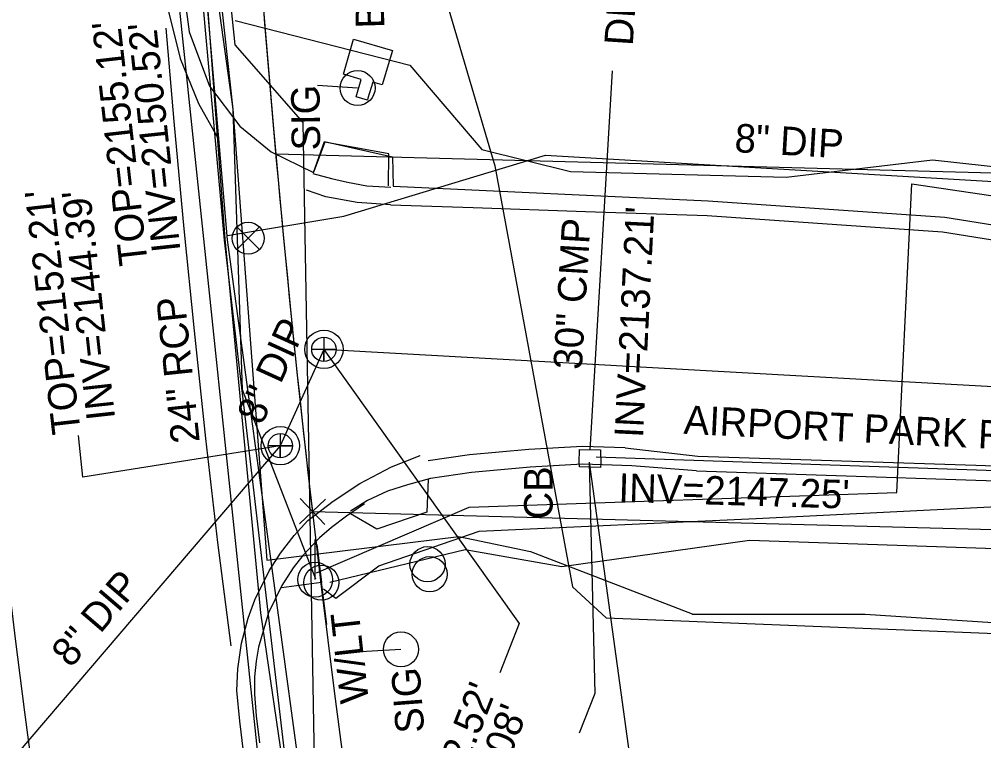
# Model space of a CAD drawing. Extents: x 945964 to 948456, y 631061 to 636061.
# Drawn here: x 946824.1 to 946959.3, y 632629.6 to 632730.8 of the extents above; entities that cross this region are included whole.
import ezdxf

# ---------------------------------------------------------------- set-up
doc = ezdxf.new("R2010")
doc.units = 0
for name, color, linetype in [('Exist Boundary County Line', 7, 'Continuous'), ('Exist Horizontal Alignment', 7, 'Continuous'), ('Exist Other Culture Area Outline', 7, 'Continuous'), ('Exist Other Culture Area Outline Text', 7, 'Continuous'), ('Exist Property Corner CELL', 7, 'Continuous'), ('Exist Property Line', 7, 'Continuous'), ('Exist Right of Way Line', 7, 'Continuous'), ('Exist Roads Curbs', 7, 'Continuous'), ('Exist Roads EOP', 7, 'Continuous'), ('Exist Roads EOP Other', 7, 'Continuous'), ('Exist Roads EOP Text', 7, 'Continuous'), ('Exist Roads EOT', 7, 'Continuous'), ('Exist Structure Minor Catch Basin', 7, 'Continuous'), ('Exist Structure Minor Catch Basin Text', 7, 'Continuous'), ('Exist Structure Minor Catch Basin Top Elevation', 7, 'Continuous'), ('Exist Structure Minor Pipes CMP 24 Inch', 7, 'Continuous'), ('Exist Structure Minor Pipes CMP 24 Inch Invert', 7, 'Continuous'), ('Exist Structure Minor Pipes CMP 30 Inch', 7, 'Continuous'), ('Exist Structure Minor Pipes CMP 30 Inch Invert', 7, 'Continuous'), ('Exist Structure Minor Pipes CMP 30 Inch Text', 7, 'Continuous'), ('Exist Structure Minor Pipes RCP 24 Inch', 7, 'Continuous'), ('Exist Structure Minor Pipes RCP 24 Inch Invert', 7, 'Continuous'), ('Exist Structure Minor Pipes RCP 24 Inch Text', 7, 'Continuous'), ('Exist Utilities Gas UG Line SUE', 7, 'Continuous'), ('Exist Utilities Other Pole CELL', 7, 'Continuous'), ('Exist Utilities Other Pole Text', 7, 'Continuous'), ('Exist Utilities Power Joint Use Telephone CELL', 7, 'Continuous'), ('Exist Utilities Power Joint Use Telephone Text', 7, 'Continuous'), ('Exist Utilities Power Pole CELL', 7, 'Continuous'), ('Exist Utilities Power UG Cable SUE', 7, 'Continuous'), ('Exist Utilities Sanitary Sewer Manhole CELL', 7, 'Continuous'), ('Exist Utilities Sanitary Sewer Manhole Leader', 7, 'Continuous'), ('Exist Utilities Sanitary Sewer Manhole Text', 7, 'Continuous'), ('Exist Utilities Sanitary Sewer UG Line', 7, 'Continuous'), ('Exist Utilities Sanitary Sewer UG Line Invert Elevation', 7, 'Continuous'), ('Exist Utilities Sanitary Sewer UG Line Text', 7, 'Continuous'), ('Exist Utilities Telephone UG Cable SUE', 7, 'Continuous'), ('Exist Utilities Telephone UG FO SUE', 7, 'Continuous'), ('Exist Utilities TV UG Cable SUE', 7, 'Continuous'), ('Exist Utilities Water UG Line SUE', 7, 'Continuous'), ('Exist Utilities Water UG Line SUE Text', 7, 'Continuous'), ('Exist Utilities Water Valve CELL', 7, 'Continuous')]:
    doc.layers.add(name, color=color, linetype=linetype)

# ---------------------------------------------------------------- blocks, each defined once
blk = doc.blocks.new('EXIST UTILITIES POWER POLE')
at = {"layer": 'Exist Utilities Power Pole CELL'}
for q in [(0, 0.1125), (0, 0)]:
    blk.add_line((0, 0), q, dxfattribs=at)
blk.add_circle((0, 0), 0.049, dxfattribs=at)
blk = doc.blocks.new('EXIST UTILITIES POWER JOINT USE TELEPHONE')
at = {"layer": 'Exist Utilities Power Joint Use Telephone CELL'}
blk.add_line((0, 0), (0, 0), dxfattribs=at)
blk.add_lwpolyline([(-0.1188, 0), (0.108, -0.0008), (0, -0.0004), (0, 0.1125)], dxfattribs=at)
blk.add_circle((0, 0.0001), 0.049, dxfattribs=at)

msp = doc.modelspace()

# ---------------------------------------------------------------- linework, layer by layer
at = {"layer": 'Exist Boundary County Line'}
msp.add_line((946865.22, 632661.77), (947116.03, 632655.16), dxfattribs=at)
msp.add_arc((948848.33, 632890.69), 1996.28, 184.06017, 186.58486, dxfattribs=at)
at = {"layer": 'Exist Horizontal Alignment'}
msp.add_arc((948718.82, 632879.65), 1909.86, 158.53343, 198.31343, dxfattribs=at)
at = {"layer": 'Exist Other Culture Area Outline'}
msp.add_lwpolyline([(946876.44, 632726.41), (946875, 632721.59), (946873.67, 632721.98), (946873.01, 632719.73), (946872.93, 632719.46), (946871.36, 632719.91), (946872.07, 632722.35), (946869.57, 632723.08), (946870.99, 632728)], close=True, dxfattribs=at)
at = {"layer": 'Exist Property Corner CELL'}
msp.add_line((946865.22, 632661.77), (946865.22, 632661.77), dxfattribs=at)
msp.add_lwpolyline([(946867.04, 632663.49), (946863.41, 632660.05), (946865.22, 632661.77), (946866.94, 632659.96), (946863.5, 632663.58)], dxfattribs=at)
at = {"layer": 'Exist Property Line'}
msp.add_line((946865.22, 632661.77), (947116.03, 632655.16), dxfattribs=at)
at = {"layer": 'Exist Right of Way Line'}
msp.add_line((946860.08, 632711.92), (947121.14, 632705.04), dxfattribs=at)
for radius, start in [(2096.28, 158.90258), (1996.28, 171.75828)]:
    msp.add_arc((948848.33, 632890.69), radius, start, 198.31343, dxfattribs=at)
at = {"layer": 'Exist Roads Curbs'}
for points in [[(946846.62, 632738.85), (946847.93, 632729), (946850.81, 632721.41), (946850.81, 632721.41), (946855.05, 632715.78), (946855.05, 632715.78), (946859.42, 632712.2), (946859.42, 632712.2), (946865.36, 632709.28), (946865.36, 632709.28), (946866.9, 632713.62), (946876.43, 632711.51), (946876.56, 632707.39), (946920.69, 632705.34)], [(946865.29, 632709.15), (946867.89, 632708.44), (946870.16, 632707.94), (946872.87, 632707.41), (946876.24, 632707.26)], [(946920.69, 632705.34), (946953.92, 632703.03), (946991.05, 632697.11), (947030.54, 632691.4), (947077.23, 632689.71), (947108.79, 632688.67), (947121.81, 632688.32)], [(946919.09, 632667.47), (946910.02, 632668.15), (946903.11, 632668.39), (946895.77, 632667.98), (946887.55, 632667.22), (946881.8, 632666.39)], [(946919.09, 632667.47), (946958.23, 632666.16), (946999.64, 632664.8), (947044.7, 632663.37), (947090.93, 632661.91), (947118.18, 632660.82)], [(946881.8, 632666.39), (946878.57, 632665.49), (946875.76, 632664.6), (946872.94, 632663.29), (946870.57, 632661.79)], [(946872.52, 632662.84), (946869.98, 632661.09), (946867.88, 632659.53), (946866.21, 632658.08), (946866.21, 632658.08), (946863.86, 632655.59), (946863.86, 632655.59), (946862.54, 632653.88), (946862.54, 632653.88), (946860.93, 632651.38), (946860.93, 632651.38), (946859.08, 632647.54), (946859.08, 632647.54), (946857.66, 632642.73), (946857.66, 632642.73), (946857.33, 632640.77), (946857.33, 632640.77), (946857.12, 632638.57), (946857.12, 632638.57), (946857.08, 632636.17), (946857.08, 632636.17), (946857.33, 632633.12), (946857.33, 632633.12), (946857.79, 632629.35)]]:
    msp.add_lwpolyline(points, dxfattribs=at)
at = {"layer": 'Exist Roads EOP'}
for points in [[(946838.69, 632880.41), (946838.99, 632838.5), (946840.08, 632810.26), (946840.15, 632806.84), (946841.49, 632776.12), (946844.15, 632739.37), (946844.51, 632735.59), (946844.98, 632732.05), (946844.98, 632732.05), (946846.66, 632725.29), (946846.66, 632725.29), (946849.24, 632718.98), (946849.24, 632718.98), (946851.83, 632714.41), (946851.83, 632714.41)], [(946876.16, 632704.76), (946871.48, 632705.09), (946867.08, 632705.87), (946864.37, 632706.82)], [(946876.16, 632704.76), (946887.77, 632704.41), (946903.52, 632703.82), (946920.55, 632703.29)], [(946920.55, 632703.29), (946953.58, 632701), (946990.71, 632695.02), (947030.31, 632689.26), (947077.14, 632687.69), (947098.06, 632686.95), (947118.43, 632686.6), (947118.43, 632686.16), (947121.73, 632685.88), (947121.74, 632686.3), (947123.84, 632686.1)], [(946909.07, 632670.69), (946903.08, 632670.89), (946895.59, 632670.47), (946887.25, 632669.71), (946881.44, 632668.87)], [(946909.07, 632670.69), (946919.28, 632669.53)], [(946855.54, 632628.11), (946855.05, 632632.37), (946854.61, 632636.67), (946854.76, 632639.69), (946854.76, 632639.69), (946855.3, 632643.3), (946855.3, 632643.3), (946856.22, 632646.8), (946856.22, 632646.8), (946857.17, 632649.4), (946857.17, 632649.4), (946859.17, 632653.46), (946859.17, 632653.46), (946860.74, 632655.93), (946860.74, 632655.93), (946862.65, 632658.41), (946862.65, 632658.41), (946864.58, 632660.49), (946864.58, 632660.49), (946866.36, 632661.87), (946868.11, 632663.22), (946868.11, 632663.22), (946871.87, 632665.71), (946871.87, 632665.71), (946876.3, 632668.01), (946876.3, 632668.01), (946880.35, 632669.62), (946880.35, 632669.62)], [(946919.28, 632669.53), (946958.23, 632668.27), (946999.9, 632666.82), (947044.72, 632665.42), (947090.96, 632663.98), (947118.77, 632662.77)]]:
    msp.add_lwpolyline(points, dxfattribs=at)
at = {"layer": 'Exist Roads EOP Other'}
for points in [[(946875.9, 632707.41), (946875.92, 632711.91), (946866.97, 632713.53), (946865.43, 632709.42)], [(946881.47, 632666.28), (946881.26, 632661.66), (946874.26, 632659.28), (946870.55, 632661.45)]]:
    msp.add_lwpolyline(points, dxfattribs=at)
at = {"layer": 'Exist Roads EOT'}
msp.add_lwpolyline([(946853.83, 632642.93), (946851.94, 632657.4), (946850.26, 632672.01), (946848.67, 632687.12), (946847.26, 632701.39), (946845.82, 632716.44), (946844.73, 632729.51)], dxfattribs=at)
at = {"layer": 'Exist Structure Minor Catch Basin'}
msp.add_line((946902.65, 632670.47), (946905.61, 632670.39), dxfattribs=at)
msp.add_lwpolyline([(946905.61, 632670.39), (946905.67, 632668.51), (946905.61, 632667.92), (946902.65, 632668.01), (946902.64, 632668.57), (946902.65, 632670.47)], dxfattribs=at)
at = {"layer": 'Exist Structure Minor Pipes CMP 24 Inch'}
msp.add_line((947119.08, 632662.1), (946905, 632669.37), dxfattribs=at)
at = {"layer": 'Exist Structure Minor Pipes CMP 30 Inch'}
for p, q in [((946904.18, 632670.38), (946907.31, 632723.54)), ((946904.02, 632668.67), (946928.64, 632489.27))]:
    msp.add_line(p, q, dxfattribs=at)
at = {"layer": 'Exist Structure Minor Pipes CMP 30 Inch Invert'}
msp.add_lwpolyline([(946904.02, 632668.67), (946904.8, 632636.27), (946902.61, 632630.68)], dxfattribs=at)
at = {"layer": 'Exist Structure Minor Pipes RCP 24 Inch'}
msp.add_line((946859.33, 632610.91), (946846.2, 632736.06), dxfattribs=at)
at = {"layer": 'Exist Utilities Gas UG Line SUE'}
for points in [[(946946.02, 632290.11), (946927.48, 632348.33), (946918.8, 632381.36), (946891.12, 632487.29), (946880.5, 632542.4), (946865.51, 632626.8), (946863.92, 632716.3), (946854.37, 632727.21), (946849.91, 632770.49), (946845.5, 632898.11)], [(946854.38, 632730.61), (946878.9, 632724.35), (946888.96, 632712.5), (946901.39, 632709.45), (946931.63, 632708.64), (946952.17, 632711.09), (947056.49, 632699.6), (947119.79, 632694.6)]]:
    msp.add_lwpolyline(points, dxfattribs=at)
at = {"layer": 'Exist Utilities Other Pole CELL'}
for centre in [(946881.36, 632654.38), (946881.67, 632652.98)]:
    msp.add_circle(centre, 2.46, dxfattribs=at)
at = {"layer": 'Exist Utilities Power Pole CELL'}
for q in [(946865.61, 632657.85), (946865.61, 632652.22)]:
    msp.add_line((946865.61, 632652.22), q, dxfattribs=at)
msp.add_circle((946865.61, 632652.22), 2.45, dxfattribs=at)
at = {"layer": 'Exist Utilities Power UG Cable SUE'}
msp.add_lwpolyline([(946867.68, 632651.85), (946886.65, 632656.46), (946900.18, 632654.06), (946926.52, 632657.77), (947071.3, 632652.86), (947115.12, 632645.49), (947119.12, 632643.31)], dxfattribs=at)
at = {"layer": 'Exist Utilities Sanitary Sewer Manhole CELL'}
for points in [[(946866.83, 632686.21), (946866.83, 632682.79), (946866.83, 632684.5), (946868.54, 632684.5), (946865.12, 632684.5)], [(946860.72, 632672.7), (946860.72, 632669.28), (946860.72, 632670.99), (946862.43, 632670.99), (946859.01, 632670.99)]]:
    msp.add_lwpolyline(points, dxfattribs=at)
for centre, radius in [((946866.83, 632684.5), 2.69), ((946866.83, 632684.5), 1.71), ((946860.72, 632670.99), 2.69), ((946860.72, 632670.99), 1.71)]:
    msp.add_circle(centre, radius, dxfattribs=at)
at = {"layer": 'Exist Utilities Sanitary Sewer Manhole Leader'}
msp.add_lwpolyline([(946866.83, 632684.5), (946894.19, 632646.05), (946891.52, 632639.16)], dxfattribs=at)
at = {"layer": 'Exist Utilities Sanitary Sewer Manhole Text'}
msp.add_lwpolyline([(946860.72, 632670.99), (946833.04, 632666.6), (946832.43, 632672.4)], dxfattribs=at)
at = {"layer": 'Exist Utilities Sanitary Sewer UG Line'}
for points in [[(946866.83, 632684.5), (946860.72, 632670.99)], [(947109.83, 632670.91), (946866.83, 632684.5)], [(946860.72, 632670.99), (946776.2, 632572.15)]]:
    msp.add_lwpolyline(points, dxfattribs=at)
at = {"layer": 'Exist Utilities Telephone UG Cable SUE'}
for points in [[(946846.26, 632860.11), (946844.71, 632858.94), (946847.42, 632778.78), (946854.07, 632718.18), (946858.84, 632654.94), (946885.75, 632658.26), (946895.82, 632656.18), (946918.45, 632647.4), (946918.48, 632647.38), (946942.74, 632647.38), (947002.13, 632643.49), (947094.19, 632645.23), (947111.49, 632643.77), (947133.12, 632623.39)], [(946865.69, 632652.29), (946855.43, 632678.82), (946854.13, 632718.17), (946847.65, 632764.68), (946844.77, 632807.04), (946848.23, 632860.46)], [(946865.8, 632653.19), (946887.18, 632662.39), (946947.15, 632664.45), (946949.26, 632707.71), (947020.8, 632697.15), (947078.03, 632693.53), (947091.15, 632697.49), (947097.51, 632705.18), (947117.74, 632769.34), (947132.19, 632833.4)]]:
    msp.add_lwpolyline(points, dxfattribs=at)
at = {"layer": 'Exist Utilities Telephone UG FO SUE'}
for points in [[(946945.37, 632289.56), (946926.37, 632347.25), (946915.58, 632381.17), (946887.96, 632487.4), (946877.32, 632541.5), (946863.2, 632626.97), (946853.33, 632699.85), (946847.31, 632769.72), (946843.75, 632861.86)], [(946866.76, 632650.93), (946868.49, 632649.63), (946874.53, 632654.13), (946888.62, 632658.99), (946927.43, 632660.77), (946966.87, 632662.77), (947007.28, 632662.23), (947046.72, 632661.06), (947084.24, 632658.76), (947125.33, 632653.79), (947134.42, 632646.48), (947152.38, 632611.74), (947179.3, 632600.22), (947205.23, 632602.91), (947220.06, 632608.42)]]:
    msp.add_lwpolyline(points, dxfattribs=at)
at = {"layer": 'Exist Utilities TV UG Cable SUE'}
msp.add_lwpolyline([(946847.41, 632858.4), (946868.78, 632784.91), (946890.8, 632710.21), (946901.69, 632651.2), (946906.41, 632646.88), (946977.26, 632643.99), (947104.81, 632643.74), (947116.69, 632637.06)], dxfattribs=at)
at = {"layer": 'Exist Utilities Water UG Line SUE'}
for points in [[(946861.6, 632622.99), (946857.97, 632647.58), (946852.97, 632699.99), (946849.46, 632747.01), (946843.88, 632853.23), (946844.6, 632925.42), (946848.49, 633021.71), (946854.67, 633094.54), (946866.27, 633169.12), (946869.9, 633189.05), (946879.92, 633250.64), (946895.59, 633320.41), (946906.54, 633358.29), (946922.14, 633411.44), (946948.63, 633497.92), (946975.56, 633562.66), (947003.55, 633599.53), (947037.06, 633649.36)], [(946940.24, 632288.02), (946920.69, 632346.69), (946911.49, 632380.68), (946887.29, 632483.85), (946876.06, 632541.06), (946861.47, 632626.94), (946852.91, 632699.82), (946846.58, 632769.64), (946842.74, 632859.23)], [(946853.32, 632700.44), (946869.63, 632703.16), (946897.9, 632711.71), (946963.88, 632707.85), (947035.99, 632697.67), (947076.9, 632696.24), (947119.46, 632692.83)]]:
    msp.add_lwpolyline(points, dxfattribs=at)
at = {"layer": 'Exist Utilities Water Valve CELL'}
msp.add_lwpolyline([(946857.79, 632701.66), (946854.64, 632698.51), (946856.21, 632700.08), (946857.79, 632698.51), (946854.64, 632701.66)], dxfattribs=at)
msp.add_circle((946856.21, 632700.08), 2.23, dxfattribs=at)

# ---------------------------------------------------------------- block references
at = {"layer": 'Exist Utilities Power Joint Use Telephone CELL', "xscale": 50, "yscale": 50, "rotation": 97.43833206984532}
msp.add_blockref('EXIST UTILITIES POWER JOINT USE TELEPHONE', (946866.48, 632651.79), dxfattribs=at)
at = {"layer": 'Exist Utilities Power Pole CELL', "xscale": 50.00000000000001, "yscale": 50.000000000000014}
for p, rotation in [((946871.55, 632721.13), 86.10396128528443), ((946877.63, 632642.43), 93.47752247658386)]:
    msp.add_blockref('EXIST UTILITIES POWER POLE', p, dxfattribs=dict(at, rotation=rotation))

# ---------------------------------------------------------------- texts
at = {"layer": 'Exist Other Culture Area Outline Text'}
msp.add_text('BOX', height=4, rotation=91.5673, dxfattribs=at).set_placement((946875.32, 632729.55))
at = {"layer": 'Exist Roads EOP Text'}
msp.add_text('AIRPORT PARK ROAD', height=4, rotation=357.2072, dxfattribs=at).set_placement((946917.21, 632672.67))
at = {"layer": 'Exist Structure Minor Catch Basin Text'}
msp.add_text('CB', height=4, rotation=90, dxfattribs=at).set_placement((946898.9, 632660.66))
at = {"layer": 'Exist Structure Minor Catch Basin Top Elevation'}
msp.add_text("TOP=2155.12'", height=4, rotation=96.5016, dxfattribs=at).set_placement((946842.15, 632696.48))
at = {"layer": 'Exist Structure Minor Pipes CMP 24 Inch Invert'}
msp.add_text("INV=2147.25'", height=4, rotation=358.313, dxfattribs=at).set_placement((946908.1, 632663.12))
at = {"layer": 'Exist Structure Minor Pipes CMP 30 Inch Invert'}
for s, rotation, p in [('DIRECTIONAL', 86.1767, (946910.13, 632726.99)), ("INV=2137.21'", 87.1664, (946911.57, 632672.04))]:
    msp.add_text(s, height=4, rotation=rotation, dxfattribs=at).set_placement(p)
at = {"layer": 'Exist Structure Minor Pipes CMP 30 Inch Text'}
msp.add_text('30" CMP', height=4, rotation=86.6298, dxfattribs=at).set_placement((946902.99, 632681.58))
at = {"layer": 'Exist Structure Minor Pipes RCP 24 Inch Invert'}
msp.add_text("INV=2150.52'", height=4, rotation=96.0818, dxfattribs=at).set_placement((946846.72, 632698.32))
at = {"layer": 'Exist Structure Minor Pipes RCP 24 Inch Text'}
msp.add_text('24" RCP', height=4, rotation=95.9886, dxfattribs=at).set_placement((946849.43, 632671.55))
at = {"layer": 'Exist Utilities Other Pole Text'}
for rotation, p in [(90.6494, (946866.32, 632712.41)), (94.3324, (946880.93, 632630.84))]:
    msp.add_text('SIG', height=4, rotation=rotation, dxfattribs=at).set_placement(p)
at = {"layer": 'Exist Utilities Power Joint Use Telephone Text'}
msp.add_text('W/LT', height=4, rotation=96.367, dxfattribs=at).set_placement((946873.14, 632635.12))
at = {"layer": 'Exist Utilities Sanitary Sewer Manhole Text'}
for s, rotation, p in [("TOP=2152.21'", 96.506, (946832.74, 632672.81)), ("TOP=2152.52'", 68.6689, (946878.54, 632604.62))]:
    msp.add_text(s, height=4, rotation=rotation, dxfattribs=at).set_placement(p)
at = {"layer": 'Exist Utilities Sanitary Sewer UG Line Invert Elevation'}
for s, rotation, p in [("INV=2144.39'", 96.2875, (946837.57, 632674.8)), ("INV=2145.08'", 68.84, (946883.77, 632603.48))]:
    msp.add_text(s, height=4, rotation=rotation, dxfattribs=at).set_placement(p)
at = {"layer": 'Exist Utilities Sanitary Sewer UG Line Text'}
for rotation, p in [(65.5021, (946858.12, 632673.74)), (49.4665, (946831.34, 632639.71))]:
    msp.add_text('8" DIP', height=4, rotation=rotation, dxfattribs=at).set_placement(p)
at = {"layer": 'Exist Utilities Water UG Line SUE Text'}
msp.add_text('8" DIP', height=4, rotation=356.6559, dxfattribs=at).set_placement((946924.34, 632712.17))

doc.saveas('drawing.dxf')
